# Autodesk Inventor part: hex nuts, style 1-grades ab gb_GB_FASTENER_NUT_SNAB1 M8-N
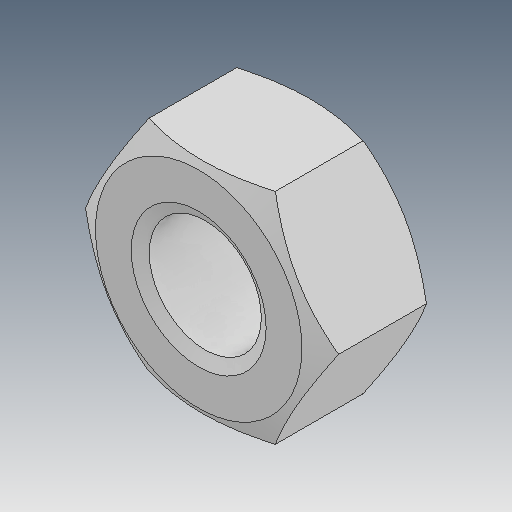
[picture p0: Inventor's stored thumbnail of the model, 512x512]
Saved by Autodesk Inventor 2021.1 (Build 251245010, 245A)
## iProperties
Created: 2019-04
Part Number: hex nuts, style 1-grades ab gb_GB_FASTENER_NUT_SNAB1 M8-N
Material: Ogólny
Document SubType Name: Modeling
Designer: user
Density: 1 g/cm^3
Appearance: Domyślna
Author: user
Revision Number: ÈÎºÎ
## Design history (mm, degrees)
feature "ÊäÈë1"
node "Bryła1"
